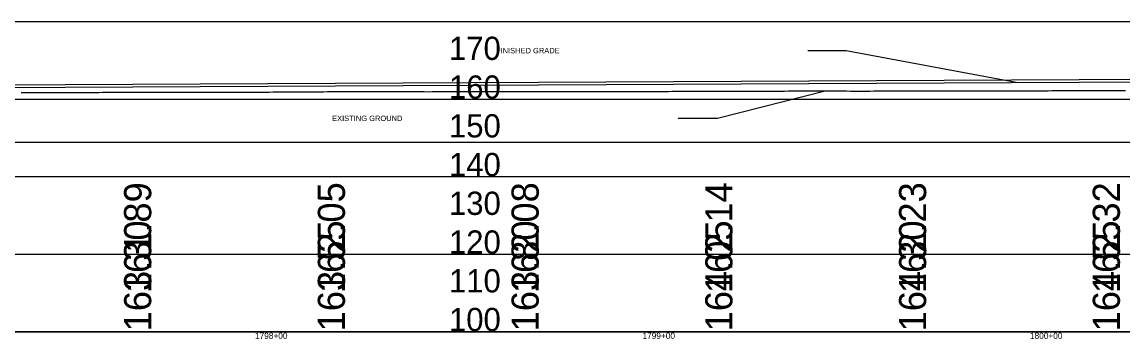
# Model space of a CAD drawing. Extents: x 2126510 to 2136144, y 865066 to 868066.
# Drawn here: x 2132338.7 to 2132622.5, y 867812.5 to 867894.3 of the extents above; entities that cross this region are included whole.
import ezdxf

# ---------------------------------------------------------------- set-up
doc = ezdxf.new("R2010")
doc.units = 0
for name, color, linetype in [('RD_EX_GuardRail', 7, 'Continuous'), ('RD_EX_H2O', 7, 'Continuous'), ('RD_EX_Misc', 7, 'Continuous'), ('RD_EX_UT', 7, 'Continuous')]:
    doc.layers.add(name, color=color, linetype=linetype)

msp = doc.modelspace()

# ---------------------------------------------------------------- linework, layer by layer
at = {"layer": 'RD_EX_GuardRail'}
for p, q in [((2135251.98, 867894.32), (2130671.73, 867894.32)), ((2133154.24, 867874.32), (2130671.73, 867874.32)), ((2135251.98, 867854.32), (2130671.73, 867854.32)), ((2135251.98, 867834.32), (2130671.73, 867834.32)), ((2135251.98, 867814.32), (2130671.73, 867814.32))]:
    msp.add_line(p, q, dxfattribs=at)
at = {"layer": 'RD_EX_H2O'}
for points in [[(2132391.47, 867876.21), (2132392.47, 867876.21), (2132393.47, 867876.21), (2132394.47, 867876.21), (2132395.47, 867876.21), (2132396.47, 867876.21), (2132397.47, 867876.21), (2132398.47, 867876.21), (2132399.47, 867876.22), (2132400.47, 867876.22), (2132401.47, 867876.23), (2132402.47, 867876.24), (2132403.47, 867876.25), (2132404.47, 867876.25), (2132405.47, 867876.26), (2132406.47, 867876.27), (2132407.47, 867876.27), (2132408.47, 867876.28), (2132409.47, 867876.29), (2132410.47, 867876.29), (2132411.47, 867876.3), (2132412.47, 867876.31), (2132413.47, 867876.31), (2132414.47, 867876.32), (2132415.47, 867876.33), (2132416.47, 867876.33), (2132417.47, 867876.34), (2132418.47, 867876.35), (2132419.47, 867876.35), (2132420.47, 867876.36), (2132421.47, 867876.36), (2132422.47, 867876.37), (2132423.47, 867876.36), (2132424.47, 867876.36), (2132425.47, 867876.36), (2132426.47, 867876.36), (2132427.47, 867876.36), (2132428.47, 867876.36), (2132429.47, 867876.36), (2132430.47, 867876.36), (2132431.47, 867876.36), (2132432.47, 867876.36), (2132433.47, 867876.35), (2132434.47, 867876.35), (2132435.47, 867876.35), (2132436.47, 867876.35), (2132437.47, 867876.35), (2132438.47, 867876.34), (2132439.47, 867876.34), (2132440.47, 867876.34), (2132441.47, 867876.34), (2132442.47, 867876.34), (2132443.47, 867876.33), (2132444.47, 867876.34), (2132445.47, 867876.34), (2132446.47, 867876.34), (2132447.47, 867876.34), (2132448.47, 867876.35), (2132449.47, 867876.35), (2132450.47, 867876.35), (2132451.47, 867876.35), (2132452.47, 867876.36), (2132453.47, 867876.36), (2132454.47, 867876.36), (2132455.47, 867876.36), (2132456.47, 867876.37), (2132457.47, 867876.37), (2132458.47, 867876.37), (2132459.47, 867876.38), (2132460.47, 867876.38), (2132461.47, 867876.38), (2132462.47, 867876.39), (2132463.47, 867876.39), (2132464.47, 867876.39), (2132465.47, 867876.39), (2132466.47, 867876.39), (2132467.47, 867876.39), (2132468.47, 867876.39), (2132469.47, 867876.39), (2132470.47, 867876.39), (2132471.47, 867876.39), (2132472.47, 867876.39), (2132473.47, 867876.39), (2132474.47, 867876.39), (2132475.47, 867876.39), (2132476.47, 867876.39), (2132477.47, 867876.39), (2132478.47, 867876.38), (2132479.47, 867876.38), (2132480.47, 867876.38), (2132481.47, 867876.38), (2132482.47, 867876.37), (2132483.47, 867876.37), (2132484.47, 867876.37), (2132485.47, 867876.37), (2132486.47, 867876.37), (2132487.47, 867876.37), (2132488.47, 867876.38), (2132489.47, 867876.38), (2132490.47, 867876.38), (2132491.47, 867876.38)], [(2132491.47, 867876.38), (2132492.47, 867876.39), (2132493.47, 867876.39), (2132494.47, 867876.39), (2132495.47, 867876.39), (2132496.47, 867876.4), (2132497.47, 867876.4), (2132498.47, 867876.4), (2132499.47, 867876.4), (2132500.47, 867876.4), (2132501.47, 867876.41), (2132502.47, 867876.41), (2132503.47, 867876.41), (2132504.47, 867876.41), (2132505.47, 867876.41), (2132506.47, 867876.42), (2132507.47, 867876.42), (2132508.47, 867876.42), (2132509.47, 867876.42), (2132510.47, 867876.42), (2132511.47, 867876.43), (2132512.47, 867876.43), (2132513.47, 867876.43), (2132514.47, 867876.43), (2132515.47, 867876.43), (2132516.47, 867876.44), (2132517.47, 867876.44), (2132518.47, 867876.44), (2132519.47, 867876.44), (2132520.47, 867876.44), (2132521.47, 867876.45), (2132522.47, 867876.45), (2132523.47, 867876.45), (2132524.47, 867876.45), (2132525.47, 867876.46), (2132526.47, 867876.46), (2132527.47, 867876.46), (2132528.47, 867876.47), (2132529.47, 867876.47), (2132530.47, 867876.47), (2132531.47, 867876.48), (2132532.47, 867876.48), (2132533.47, 867876.49), (2132534.47, 867876.5), (2132535.47, 867876.5), (2132536.47, 867876.51), (2132537.47, 867876.51), (2132538.47, 867876.52), (2132539.47, 867876.52), (2132540.47, 867876.53), (2132541.47, 867876.53), (2132542.47, 867876.54), (2132543.47, 867876.53), (2132544.47, 867876.53), (2132545.47, 867876.53), (2132546.47, 867876.52), (2132547.47, 867876.52), (2132548.47, 867876.52), (2132549.47, 867876.51), (2132550.47, 867876.51), (2132551.47, 867876.51), (2132552.47, 867876.5), (2132553.47, 867876.5), (2132554.47, 867876.5), (2132555.47, 867876.5), (2132556.47, 867876.5), (2132557.47, 867876.5), (2132558.47, 867876.51), (2132559.47, 867876.51), (2132560.47, 867876.51), (2132561.47, 867876.51), (2132562.47, 867876.51), (2132563.47, 867876.52), (2132564.47, 867876.52), (2132565.47, 867876.52), (2132566.47, 867876.53), (2132567.47, 867876.53), (2132568.47, 867876.53), (2132569.47, 867876.54), (2132570.47, 867876.54), (2132571.47, 867876.54), (2132572.47, 867876.55), (2132573.47, 867876.55), (2132574.47, 867876.55), (2132575.47, 867876.56), (2132576.47, 867876.56), (2132577.47, 867876.56), (2132578.47, 867876.56), (2132579.47, 867876.56), (2132580.47, 867876.55), (2132581.47, 867876.55), (2132582.47, 867876.55), (2132583.47, 867876.55), (2132584.47, 867876.55), (2132585.47, 867876.55), (2132586.47, 867876.54), (2132587.47, 867876.54), (2132588.47, 867876.54), (2132589.47, 867876.55), (2132590.47, 867876.55), (2132591.47, 867876.55)], [(2132591.47, 867876.55), (2132592.47, 867876.55), (2132593.47, 867876.55), (2132594.47, 867876.55), (2132595.47, 867876.55), (2132596.47, 867876.55), (2132597.47, 867876.55), (2132598.47, 867876.55), (2132599.47, 867876.55), (2132600.47, 867876.56), (2132601.47, 867876.57), (2132602.47, 867876.58), (2132603.47, 867876.59), (2132604.47, 867876.6), (2132605.47, 867876.6), (2132606.47, 867876.61), (2132607.47, 867876.62), (2132608.47, 867876.63), (2132609.47, 867876.63), (2132610.47, 867876.63), (2132611.47, 867876.63), (2132612.47, 867876.63), (2132613.47, 867876.64), (2132614.47, 867876.64), (2132615.47, 867876.64), (2132616.47, 867876.64), (2132617.47, 867876.64), (2132618.47, 867876.64), (2132619.47, 867876.64), (2132620.47, 867876.64), (2132621.47, 867876.64), (2132622.47, 867876.64), (2132623.47, 867876.64)], [(2132338.47, 867876.12), (2132339.47, 867876.12), (2132340.47, 867876.13), (2132341.47, 867876.13), (2132342.47, 867876.13), (2132343.47, 867876.13), (2132344.47, 867876.13), (2132345.47, 867876.12), (2132346.47, 867876.12), (2132347.47, 867876.11), (2132348.47, 867876.11), (2132349.47, 867876.11), (2132350.47, 867876.11), (2132351.47, 867876.12), (2132352.47, 867876.12), (2132353.47, 867876.13), (2132354.47, 867876.14), (2132355.47, 867876.14), (2132356.47, 867876.15), (2132357.47, 867876.16), (2132358.47, 867876.16), (2132359.47, 867876.17), (2132360.47, 867876.18), (2132361.47, 867876.18), (2132362.47, 867876.19), (2132363.47, 867876.19), (2132364.47, 867876.2), (2132365.47, 867876.21), (2132366.47, 867876.21), (2132367.47, 867876.21), (2132368.47, 867876.21), (2132369.47, 867876.21), (2132370.47, 867876.21), (2132371.47, 867876.21), (2132372.47, 867876.21), (2132373.47, 867876.21), (2132374.47, 867876.21), (2132375.47, 867876.21), (2132376.47, 867876.21), (2132377.47, 867876.21), (2132378.47, 867876.21), (2132379.47, 867876.21), (2132380.47, 867876.21), (2132381.47, 867876.21), (2132382.47, 867876.21), (2132383.47, 867876.21), (2132384.47, 867876.21), (2132385.47, 867876.21), (2132386.47, 867876.21), (2132387.47, 867876.21), (2132388.47, 867876.21), (2132389.47, 867876.21), (2132390.47, 867876.21), (2132391.47, 867876.21)]]:
    msp.add_lwpolyline(points, dxfattribs=at)
at = {"layer": 'RD_EX_Misc'}
for p, q in [((2132116.01, 867877.03), (2133296.65, 867882.93)), ((2131523, 867814.32), (2135677.25, 867814.32))]:
    msp.add_line(p, q, dxfattribs=at)
for points in [[(2132541.46, 867886.93), (2132551.39, 867886.93), (2132595.67, 867878.73)], [(2132508, 867869.45), (2132518.19, 867869.45), (2132545.97, 867876.53)], [(2131430.13, 867814.32), (2131430.13, 867863.32), (2136143.96, 867863.32)]]:
    msp.add_lwpolyline(points, dxfattribs=at)
at = {"layer": 'RD_EX_UT'}
msp.add_line((2132116.01, 867876.33), (2133296.65, 867882.24), dxfattribs=at)

# ---------------------------------------------------------------- texts
at = {"layer": 'RD_EX_Misc'}
for s, height, p in [('170', 6, (2132448.84, 867884.52)), ('FINISHED GRADE', 1.4, (2132460.99, 867886.23)), ('160', 6, (2132448.84, 867874.52)), ('150', 6, (2132448.84, 867864.52)), ('EXISTING GROUND', 1.4, (2132418.69, 867868.75)), ('140', 6, (2132448.84, 867854.52)), ('130', 6, (2132448.84, 867844.52)), ('120', 6, (2132448.84, 867834.52)), ('110', 6, (2132448.84, 867824.52)), ('100', 6, (2132448.84, 867814.52)), ('1798+00', 1.6, (2132398.79, 867812.52)), ('1799+00', 1.6, (2132498.79, 867812.52)), ('1800+00', 1.6, (2132598.79, 867812.52))]:
    msp.add_text(s, height=height, dxfattribs=at).set_placement(p)
for s, p in [('161.89', (2132372, 867824.32)), ('162.05', (2132422, 867824.32)), ('162.08', (2132472, 867824.32)), ('162.14', (2132522, 867824.32)), ('162.23', (2132572, 867824.32)), ('162.32', (2132622, 867824.32)), ('163.30', (2132372, 867814.47)), ('163.55', (2132422, 867814.47)), ('163.80', (2132472, 867814.47)), ('164.05', (2132522, 867814.47)), ('164.30', (2132572, 867814.47)), ('164.55', (2132622, 867814.47))]:
    msp.add_text(s, height=7, rotation=90, dxfattribs=at).set_placement(p)

doc.saveas('drawing.dxf')
